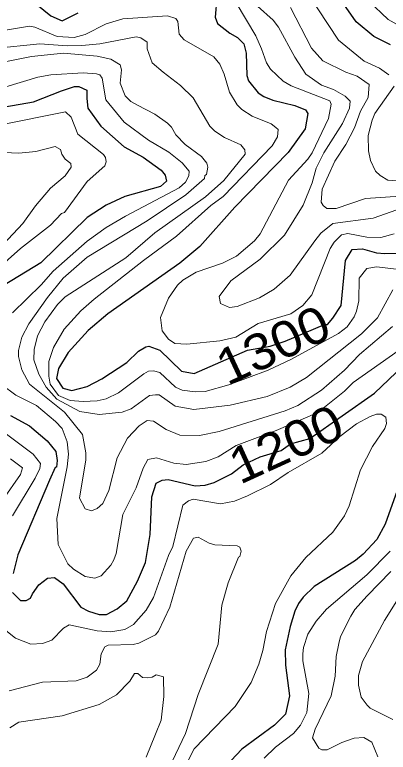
# Model space of a CAD drawing. Extents: x 423 to 448.8, y 7456.3 to 7484.
# Drawn here: x 434.009 to 434.838, y 7480.557 to 7482.192 of the extents above; entities that cross this region are included whole.
import ezdxf
from ezdxf.enums import TextEntityAlignment as Align

# ---------------------------------------------------------------- set-up
doc = ezdxf.new("R2010")
doc.units = 0
doc.header["$LTSCALE"] = 0.032
doc.layers.add('1', color=7, linetype='Continuous', lineweight=25)
doc.layers.add('2', color=7, linetype='Continuous', lineweight=13)
doc.layers.add('61', color=7, linetype='Continuous')

msp = doc.modelspace()

# ---------------------------------------------------------------- linework, layer by layer
at = {"layer": '1'}
for points in [[(434.8433, 7482.1257), (434.8061, 7482.1442), (434.7667, 7482.1768), (434.7226, 7482.2409)], [(434.4581, 7482.2301), (434.4542, 7482.1868), (434.4596, 7482.1729), (434.4867, 7482.1512), (434.5037, 7482.1419), (434.5176, 7482.128), (434.523, 7482.1072), (434.5246, 7482.0577), (434.5284, 7482.046), (434.5493, 7482.019), (434.5625, 7482.0112), (434.5818, 7482.0027), (434.6313, 7481.9911), (434.6545, 7481.9811), (434.6599, 7481.9733), (434.6537, 7481.9393), (434.6158, 7481.8867), (434.4975, 7481.7653), (434.4202, 7481.6786), (434.3761, 7481.6415), (434.216, 7481.5293), (434.1727, 7481.4922), (434.1278, 7481.4435), (434.1069, 7481.4079)], [(434.0582, 7482.2146), (434.0899, 7482.1899), (434.1147, 7482.179), (434.1503, 7482.1968)], [(433.9878, 7481.988), (434.0512, 7481.9989), (434.1131, 7482.0236), (434.1417, 7482.0329), (434.1518, 7482.0329), (434.1692, 7482.0247), (434.1696, 7482.0066), (434.1719, 7481.9849), (434.2005, 7481.9455), (434.2523, 7481.8991), (434.2941, 7481.8767), (434.3343, 7481.8473), (434.3436, 7481.8364), (434.3459, 7481.8233), (434.3328, 7481.8117), (434.2539, 7481.7892), (434.2121, 7481.7699), (434.1704, 7481.7428), (434.0675, 7481.6423), (433.9863, 7481.5928)], [(434.1069, 7481.4079), (434.1023, 7481.3855), (434.1162, 7481.3646), (434.1363, 7481.3592), (434.1704, 7481.3677), (434.2028, 7481.3847), (434.2585, 7481.4211), (434.284, 7481.4466), (434.3003, 7481.4559), (434.3072, 7481.4574), (434.3312, 7481.4489), (434.3792, 7481.4017), (434.4078, 7481.3971), (434.5257, 7481.4484), (434.576, 7481.4578), (434.6096, 7481.4685), (434.6969, 7481.5052), (434.7033, 7481.5054), (434.7156, 7481.5193), (434.7334, 7481.5479), (434.7435, 7481.6477), (434.7582, 7481.6717), (434.7814, 7481.6732), (434.8123, 7481.6647), (434.8309, 7481.6632), (434.885, 7481.6647)], [(434.4519, 7481.155), (434.4906, 7481.1743), (434.5161, 7481.1945), (434.5538, 7481.212), (434.6003, 7481.2264), (434.6216, 7481.2408), (434.664, 7481.2525), (434.8077, 7481.353), (434.8873, 7481.4296)], [(434.0002, 7481.3035), (434.042, 7481.2811), (434.0814, 7481.2478), (434.1007, 7481.2239), (434.1038, 7481.2038), (434.1023, 7481.189), (434.0992, 7481.1883), (434.0868, 7481.1604), (434.0164, 7480.9949), (434.0056, 7480.9532)], [(434.0048, 7480.9114), (434.0226, 7480.8936), (434.035, 7480.8936), (434.0443, 7480.899), (434.0489, 7480.9083), (434.0628, 7480.9284), (434.0821, 7480.9431), (434.0977, 7480.9446), (434.117, 7480.9307), (434.1564, 7480.8789), (434.1734, 7480.8696), (434.1967, 7480.8626), (434.2129, 7480.8626), (434.2369, 7480.875), (434.2585, 7480.8928), (434.2817, 7480.9361), (434.2995, 7480.9779), (434.3096, 7481.0398), (434.3134, 7481.1233), (434.3235, 7481.1535), (434.3366, 7481.1604), (434.3498, 7481.162), (434.4101, 7481.1481), (434.4318, 7481.1496), (434.4519, 7481.155)], [(434.8618, 7481.1481), (434.8317, 7481.063), (434.8131, 7481.029), (434.7829, 7480.9964), (434.7659, 7480.9825), (434.6739, 7480.9245), (434.6491, 7480.9013), (434.6391, 7480.8866), (434.6306, 7480.8696), (434.6205, 7480.8356), (434.6096, 7480.7845), (434.6104, 7480.7505), (434.6189, 7480.6824), (434.6104, 7480.6414), (434.5857, 7480.6175), (434.5137, 7480.5641), (434.4898, 7480.5385)]]:
    msp.add_lwpolyline(points, dxfattribs=at)
at = {"layer": '2'}
for points in [[(434.6592, 7482.2409), (434.728, 7482.1358), (434.7845, 7482.0893), (434.8185, 7482.0739), (434.8394, 7482.0592)], [(434.5006, 7482.2185), (434.5447, 7482.1458), (434.5571, 7482.1164), (434.5679, 7482.0855), (434.5772, 7482.0716), (434.605, 7482.0452), (434.6228, 7482.0344), (434.7087, 7482.0012), (434.7118, 7481.9942), (434.7056, 7481.9625), (434.6692, 7481.8859), (434.6599, 7481.872), (434.6166, 7481.8256), (434.554, 7481.7065), (434.5416, 7481.691), (434.5014, 7481.657), (434.4705, 7481.6415), (434.4117, 7481.6214), (434.3823, 7481.6036), (434.3707, 7481.5928), (434.3505, 7481.5642), (434.3328, 7481.5209), (434.3366, 7481.4914), (434.3505, 7481.4729), (434.3645, 7481.4636), (434.3916, 7481.462), (434.4643, 7481.469), (434.4999, 7481.4775), (434.5494, 7481.5077), (434.6221, 7481.5293), (434.6484, 7481.5479), (434.6684, 7481.5711), (434.7094, 7481.674), (434.7179, 7481.6879), (434.7342, 7481.7042), (434.7489, 7481.7072), (434.7907, 7481.6988), (434.8216, 7481.698), (434.851, 7481.7065)], [(434.7945, 7482.2232), (434.8378, 7482.1814), (434.885, 7482.1559), (434.9577, 7482.128), (434.9717, 7482.121), (434.9817, 7482.1102), (434.984, 7482.0963), (434.9763, 7482.0809), (434.9546, 7482.0515), (434.933, 7482.0082), (434.9322, 7481.9865), (434.9547, 7481.9671), (434.9686, 7481.9663), (434.9964, 7481.9733), (435.049, 7482.0027), (435.0908, 7482.0174), (435.1496, 7482.0213), (435.1913, 7482.0151), (435.2346, 7482.0058), (435.3104, 7481.981), (435.3383, 7481.9756), (435.3816, 7481.9718), (435.4419, 7481.9725), (435.558, 7481.9903)], [(434.5478, 7482.2115), (434.5826, 7482.1799), (434.595, 7482.1644), (434.6306, 7482.0979), (434.6553, 7482.0607), (434.6901, 7482.036), (434.7164, 7482.0267), (434.7427, 7482.012), (434.7535, 7482.0004), (434.752, 7481.9849), (434.7365, 7481.9509), (434.6955, 7481.8859), (434.6785, 7481.8519), (434.6692, 7481.8194), (434.6491, 7481.7699), (434.6081, 7481.7034), (434.554, 7481.65), (434.489, 7481.6021), (434.4627, 7481.5673), (434.4658, 7481.5518), (434.4859, 7481.5433), (434.503, 7481.5456), (434.5525, 7481.5649), (434.5849, 7481.5835), (434.6205, 7481.6152), (434.6754, 7481.691), (434.6886, 7481.708), (434.7156, 7481.7297), (434.8046, 7481.7413), (434.8696, 7481.7645)], [(434.8866, 7481.7916), (434.7876, 7481.7846), (434.7226, 7481.7629), (434.7017, 7481.7629), (434.694, 7481.7691), (434.6893, 7481.7769), (434.6917, 7481.8055), (434.7195, 7481.8674), (434.7442, 7481.9045), (434.7636, 7481.9416), (434.7767, 7481.9788), (434.7938, 7482.0089), (434.7961, 7482.0375), (434.769, 7482.0561), (434.7443, 7482.0646), (434.6932, 7482.0901), (434.6677, 7482.118), (434.6213, 7482.2085)], [(433.9801, 7482.1566), (434.042, 7482.1667), (434.0543, 7482.1644), (434.1038, 7482.1443), (434.141, 7482.1419), (434.1657, 7482.1481), (434.2121, 7482.1721), (434.2493, 7482.1829), (434.3483, 7482.1899), (434.3668, 7482.1837), (434.3714, 7482.1775), (434.3746, 7482.1489), (434.3854, 7482.1365), (434.4511, 7482.0986), (434.4643, 7482.0824), (434.4743, 7482.0607), (434.4859, 7482.0205), (434.5029, 7481.9926), (434.5137, 7481.9818), (434.5362, 7481.9671), (434.5787, 7481.9501), (434.5888, 7481.9424), (434.5942, 7481.9377), (434.5926, 7481.9215), (434.5803, 7481.9014), (434.472, 7481.7892), (434.4449, 7481.7691), (434.3684, 7481.7011), (434.2949, 7481.6477), (434.1858, 7481.5618), (434.1564, 7481.5355), (434.1193, 7481.4953), (434.0953, 7481.4544), (434.0853, 7481.4234), (434.0853, 7481.3909), (434.0884, 7481.3731), (434.1069, 7481.3484), (434.1324, 7481.3367), (434.1611, 7481.3344), (434.192, 7481.336), (434.2121, 7481.3406), (434.24, 7481.3538), (434.2957, 7481.3963), (434.3065, 7481.4017), (434.3173, 7481.4025), (434.3312, 7481.3994), (434.366, 7481.3669), (434.3807, 7481.36), (434.4101, 7481.3561), (434.4318, 7481.3569), (434.4844, 7481.3716), (434.5715, 7481.404), (434.6233, 7481.4284), (434.728, 7481.4853), (434.7474, 7481.5), (434.7628, 7481.5224), (434.7675, 7481.5348), (434.7729, 7481.558), (434.7737, 7481.6082), (434.7907, 7481.6299), (434.8123, 7481.633), (434.8819, 7481.6253)], [(434.3389, 7482.0646), (434.3142, 7482.0855), (434.3034, 7482.1164), (434.3034, 7482.1311), (434.2895, 7482.1411), (434.2786, 7482.1435), (434.1982, 7482.128), (434.158, 7482.1241), (434.1255, 7482.1234), (434.0652, 7482.128), (433.9631, 7482.1172)], [(433.9569, 7482.0816), (434.0466, 7482.0994), (434.1178, 7482.1071), (434.192, 7482.1002), (434.223, 7482.094), (434.2431, 7482.0808), (434.2462, 7482.07), (434.2431, 7482.0406), (434.2546, 7482.0128), (434.267, 7481.9996), (434.2817, 7481.9919), (434.3204, 7481.9718), (434.3483, 7481.9517), (434.3575, 7481.9432), (434.3668, 7481.9261), (434.3877, 7481.9045), (434.4241, 7481.8782), (434.4356, 7481.8635), (434.438, 7481.8542), (434.4349, 7481.8379), (434.431, 7481.8356), (434.4302, 7481.8295), (434.3892, 7481.7931), (434.3034, 7481.7351), (434.1704, 7481.6547), (434.117, 7481.6082), (434.0821, 7481.5657), (434.0404, 7481.507), (434.0249, 7481.4776), (434.018, 7481.4482), (434.018, 7481.4342), (434.0249, 7481.4049), (434.0419, 7481.3731), (434.1201, 7481.3112), (434.1595, 7481.2617), (434.1673, 7481.2208), (434.1673, 7481.2053), (434.1533, 7481.1202), (434.1657, 7481.097), (434.1796, 7481.0923), (434.192, 7481.0978), (434.2051, 7481.1086), (434.2183, 7481.1372), (434.2369, 7481.2099), (434.26, 7481.2533)], [(433.9894, 7482.0321), (434.0605, 7482.0538), (434.0899, 7482.0592), (434.1611, 7482.0631), (434.1905, 7482.0615), (434.1982, 7482.0592), (434.2036, 7482.0514), (434.2113, 7482.0035), (434.2523, 7481.954), (434.3064, 7481.9138), (434.3514, 7481.8875), (434.3807, 7481.8642), (434.3962, 7481.8457), (434.3954, 7481.8349), (434.3884, 7481.821), (434.3746, 7481.8086), (434.2554, 7481.7459), (434.2121, 7481.7204), (434.1704, 7481.6902), (434.0946, 7481.6237), (434.0682, 7481.5935), (434.0048, 7481.5317)], [(434.8487, 7481.5827), (434.8146, 7481.5201), (434.7791, 7481.4845), (434.6568, 7481.3878), (434.6205, 7481.3669), (434.5695, 7481.3461), (434.4875, 7481.3267), (434.407, 7481.3174), (434.3653, 7481.3244), (434.3296, 7481.3492), (434.322, 7481.3499), (434.3088, 7481.3484), (434.2678, 7481.3182), (434.2477, 7481.3112), (434.1967, 7481.3058), (434.1541, 7481.3128), (434.1031, 7481.3399), (434.079, 7481.3662), (434.0632, 7481.3951), (434.052, 7481.4274), (434.0528, 7481.4497), (434.0597, 7481.4807), (434.076, 7481.5116), (434.1046, 7481.5495), (434.1216, 7481.5665), (434.2562, 7481.6531), (434.3204, 7481.7088), (434.4325, 7481.7884), (434.4736, 7481.8248), (434.5207, 7481.8828), (434.5199, 7481.8929), (434.5114, 7481.9037), (434.4751, 7481.9199), (434.4534, 7481.9339), (434.4426, 7481.9455), (434.4055, 7482.0082), (434.3776, 7482.0352), (434.3389, 7482.0646)], [(434.851, 7482.0336), (434.8084, 7481.9733), (434.8022, 7481.9587), (434.7938, 7481.9246), (434.7945, 7481.8906), (434.7992, 7481.8689), (434.81, 7481.8457), (434.82, 7481.8356), (434.837, 7481.8256), (434.8897, 7481.8217)], [(433.9708, 7481.947), (434.1224, 7481.9772), (434.1348, 7481.9648), (434.1494, 7481.9277), (434.2067, 7481.8821), (434.2105, 7481.8759), (434.2121, 7481.8658), (434.209, 7481.8573), (434.1704, 7481.8225), (434.1201, 7481.7536), (434.1131, 7481.7513), (434.0891, 7481.7258), (434.0219, 7481.674), (433.9669, 7481.6253)], [(433.9693, 7481.8875), (434.0188, 7481.8852), (434.0559, 7481.889), (434.0992, 7481.8999), (434.1108, 7481.8936), (434.1139, 7481.8829), (434.1216, 7481.872), (434.134, 7481.8627), (434.1348, 7481.8542), (434.1216, 7481.8349), (434.0891, 7481.8078), (434.0558, 7481.7684), (434.0272, 7481.7297), (433.9723, 7481.6709)], [(434.26, 7481.2533), (434.2856, 7481.2811), (434.3034, 7481.2927), (434.3173, 7481.2911), (434.3452, 7481.2726), (434.3761, 7481.2602), (434.4194, 7481.2594), (434.4627, 7481.2679), (434.6097, 7481.3143), (434.6375, 7481.3259), (434.6901, 7481.36), (434.7412, 7481.4041), (434.7744, 7481.4389), (434.8479, 7481.5008)], [(434.0118, 7481.3491), (434.0574, 7481.3259), (434.1, 7481.2903), (434.1146, 7481.2749), (434.1255, 7481.2455), (434.1286, 7481.2177), (434.1255, 7481.1898), (434.103, 7481.0754), (434.1061, 7481.0181), (434.127, 7480.9748), (434.1402, 7480.9632), (434.1657, 7480.947), (434.1874, 7480.9431), (434.2013, 7480.9485), (434.223, 7480.9717), (434.2291, 7480.9841), (434.2345, 7480.998), (434.2492, 7481.0846), (434.2786, 7481.1434), (434.2941, 7481.1867), (434.3049, 7481.2061), (434.3243, 7481.2099), (434.3622, 7481.1983), (434.39, 7481.1952), (434.4333, 7481.2014), (434.4612, 7481.2122), (434.5006, 7481.237), (434.5892, 7481.2705), (434.6822, 7481.3103), (434.7412, 7481.3576), (434.7605, 7481.377), (434.8602, 7481.4474)], [(433.9801, 7481.3724), (434.0118, 7481.3491)], [(434.6159, 7481.1774), (434.6909, 7481.22), (434.7311, 7481.2571), (434.7675, 7481.2849), (434.7984, 7481.3012), (434.8123, 7481.3066), (434.8224, 7481.3066), (434.8332, 7481.3004), (434.834, 7481.2857), (434.8309, 7481.2749), (434.803, 7481.2347), (434.7767, 7481.1836), (434.7512, 7481.1032), (434.7412, 7481.0815), (434.7149, 7481.0452), (434.6553, 7480.9887), (434.6221, 7480.9485), (434.588, 7480.8866), (434.5679, 7480.8248), (434.5602, 7480.783), (434.5509, 7480.7521), (434.5339, 7480.7118), (434.4983, 7480.6584), (434.4078, 7480.5649), (434.3815, 7480.5138)], [(433.9909, 7481.2625), (434.0505, 7481.2177), (434.0667, 7481.1975), (434.0652, 7481.1859), (434.0551, 7481.1651), (434.0048, 7481.0815)], [(434.0002, 7481.2076), (434.0265, 7481.1875), (434.0226, 7481.1728), (433.9831, 7481.1171)], [(433.9824, 7480.8332), (434.011, 7480.81), (434.0451, 7480.7969), (434.0714, 7480.7984), (434.0915, 7480.8054), (434.1177, 7480.8325), (434.1301, 7480.8394), (434.192, 7480.8263), (434.223, 7480.824), (434.2539, 7480.8294), (434.2732, 7480.8402), (434.301, 7480.8719), (434.3173, 7480.9006), (434.3505, 7480.9934), (434.3606, 7481.0135), (434.3823, 7481.1048), (434.3947, 7481.1148), (434.4055, 7481.1179), (434.4658, 7481.1078), (434.4968, 7481.114), (434.5262, 7481.1256), (434.5772, 7481.1511), (434.6159, 7481.1774)], [(433.9971, 7480.6933), (434.0714, 7480.7126), (434.1456, 7480.7157), (434.1704, 7480.7234), (434.1912, 7480.7389), (434.1982, 7480.7521), (434.2013, 7480.7753), (434.209, 7480.7907), (434.2168, 7480.7946), (434.2725, 7480.7961), (434.2848, 7480.7992), (434.322, 7480.8178), (434.3281, 7480.8255), (434.3536, 7480.8789), (434.39, 7481.0027), (434.4062, 7481.032), (434.4163, 7481.0343), (434.4411, 7481.0204), (434.4534, 7481.0173), (434.503, 7481.015), (434.5091, 7481.0119), (434.5122, 7481.0026), (434.5091, 7480.991), (434.506, 7480.9895), (434.4828, 7480.933), (434.4689, 7480.8835), (434.4612, 7480.7969), (434.4163, 7480.6855), (434.3885, 7480.5989), (434.3591, 7480.537)], [(434.8425, 7481.0027), (434.7907, 7480.9508), (434.701, 7480.8742), (434.6785, 7480.848), (434.6599, 7480.8186), (434.6499, 7480.7892), (434.6484, 7480.7753), (434.6484, 7480.7598), (434.6623, 7480.6871), (434.6576, 7480.6453), (434.6437, 7480.6175), (434.6282, 7480.5989), (434.588, 7480.5687), (434.5632, 7480.544)], [(434.844, 7480.9578), (434.7914, 7480.9036), (434.7644, 7480.8735), (434.7551, 7480.8587), (434.7326, 7480.8139), (434.7288, 7480.7985), (434.7226, 7480.7691), (434.7203, 7480.7258), (434.7118, 7480.6824), (434.6762, 7480.6082), (434.67, 7480.5888), (434.6839, 7480.5664), (434.6909, 7480.5625), (434.7025, 7480.5625), (434.7349, 7480.5788), (434.7628, 7480.5881), (434.7844, 7480.5896), (434.8015, 7480.5795), (434.8154, 7480.5471)], [(434.8487, 7480.6298), (434.7984, 7480.6546), (434.7914, 7480.6615), (434.7783, 7480.6793), (434.7721, 7480.7056), (434.7721, 7480.7273), (434.7814, 7480.7582), (434.8301, 7480.8495), (434.8982, 7480.9578)], [(433.9986, 7480.6113), (434.0188, 7480.6236), (434.1147, 7480.6376), (434.1967, 7480.6631), (434.2353, 7480.6847), (434.2647, 7480.7149), (434.2755, 7480.7319), (434.2825, 7480.7319), (434.2926, 7480.7226), (434.3034, 7480.7219), (434.3142, 7480.7234), (434.3235, 7480.7288), (434.3397, 7480.7242), (434.3405, 7480.6809), (434.3343, 7480.6283), (434.322, 7480.5974), (434.301, 7480.5463)]]:
    msp.add_lwpolyline(points, dxfattribs=at)

# ---------------------------------------------------------------- texts
at = {"layer": '61', "width": 1.1}
for s, rotation, p in [('1300', 25.073, (434.5995, 7481.4237)), ('1200', 24.531, (434.628, 7481.2041))]:
    msp.add_text(s, height=0.08, rotation=rotation, dxfattribs=at).set_placement(p, align=Align.CENTER)

doc.saveas('drawing.dxf')
